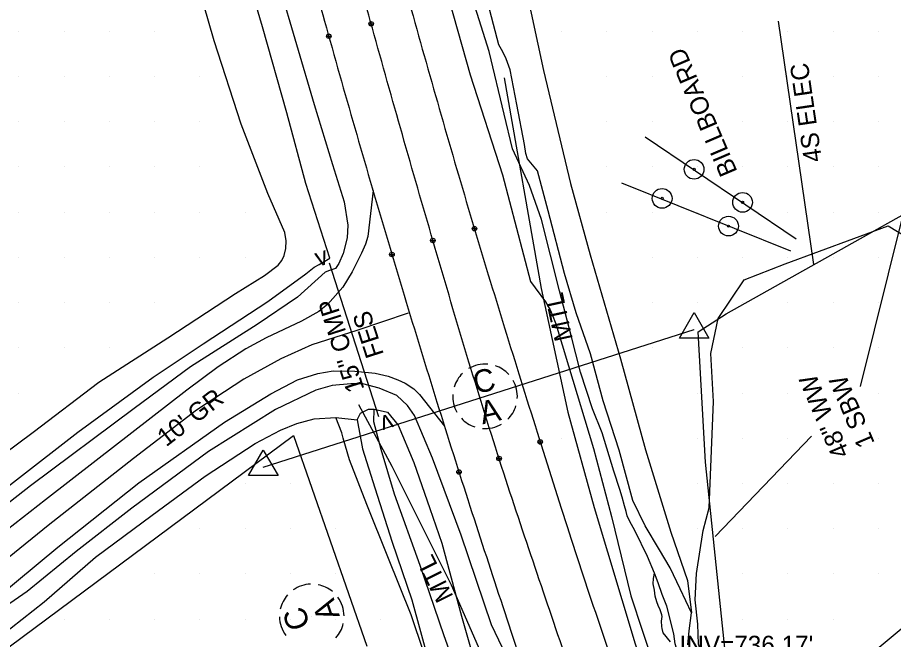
# Model space of a CAD drawing. Extents: x 1548934 to 1561348, y 809680 to 824075.
# Drawn here: x 1551639.7 to 1551833.4, y 810915.5 to 811053 of the extents above; entities that cross this region are included whole.
import ezdxf

# ---------------------------------------------------------------- set-up
doc = ezdxf.new("R2010")
doc.units = 0
for name, color, linetype in [('Default', 7, 'Continuous'), ('E_NCDOT_Vertical_Profile_Ground_Line', 7, 'Continuous'), ('Exist DTM QL2 LIDAR Elevation Point', 7, 'Continuous'), ('Exist Guardrail', 7, 'Continuous'), ('Exist Guardrail Text', 7, 'Continuous'), ('Exist Other Culture Area Outline', 7, 'Continuous'), ('Exist Other Culture Fence Line Leader', 7, 'Continuous'), ('Exist Other Culture Fence Line Text', 7, 'Continuous'), ('Exist Other Culture Sign', 7, 'Continuous'), ('Exist Other Culture Sign CELL', 7, 'Continuous'), ('Exist Other Culture Sign Text', 7, 'Continuous'), ('Exist Right of Way Control of Access CA Symbol CELL', 7, 'Continuous'), ('Exist Roads Soil', 7, 'Continuous'), ('Exist Roads Soil Text', 7, 'Continuous'), ('Exist Structure Minor Culvert Topo', 7, 'Continuous'), ('Exist Structure Minor Culvert Topo Terminator', 7, 'Continuous'), ('Exist Structure Minor Pipes CMP 15 Inch Text', 7, 'Continuous'), ('Exist Structure Minor Pipes CMP 18 Inch Invert Elevation', 7, 'Continuous'), ('Exist Vegetation Woods Line', 7, 'Continuous'), ('P_NCDOT_Vertical_Profile_Grade_Minor_Road', 7, 'Continuous'), ('P_RDY_Dimension_Text', 7, 'Continuous'), ('PH Exist DTM Breakline', 7, 'Continuous')]:
    doc.layers.add(name, color=color, linetype=linetype)

# ---------------------------------------------------------------- blocks, each defined once
blk = doc.blocks.new('SurveyPointCell')
at = {"layer": 'Default'}
for p, q in [((-0.5, 0), (0.5, 0)), ((0, -0.5), (0, 0.5))]:
    blk.add_line(p, q, dxfattribs=at)
blk.add_circle((0, 0), 0.5, dxfattribs=at)

msp = doc.modelspace()

# ---------------------------------------------------------------- linework, layer by layer
at = {"layer": 'E_NCDOT_Vertical_Profile_Ground_Line'}
for p, q in [((1551789.31, 810984.03), (1551789.31, 810984.03)), ((1551694.04, 810953.63), (1551694.04, 810953.63))]:
    msp.add_line(p, q, dxfattribs=at)
for points in [[(1551786.06, 810982.14), (1551789.31, 810987.78), (1551792.56, 810982.14)], [(1551690.79, 810951.74), (1551694.04, 810957.38), (1551697.29, 810951.74)]]:
    msp.add_lwpolyline(points, close=True, dxfattribs=at)
for points in [[(1551669.23, 811277), (1551672.74, 811263.65), (1551679.61, 811234.97), (1551690.37, 811191.22), (1551702.41, 811145.66), (1551714.33, 811100.03), (1551727, 811053.45), (1551740.47, 811006.5), (1551755.13, 810959.34), (1551769.1, 810915.85), (1551778.93, 810888.33), (1551783.17, 810876.09)], [(1551650.09, 811272.18), (1551653.54, 811258.38), (1551661.25, 811229.55), (1551671.78, 811185.41), (1551683.85, 811140.03), (1551696.07, 811094.56), (1551708.62, 811047.91), (1551722.36, 811000.57), (1551736.98, 810952.93), (1551751.55, 810908.96), (1551760.88, 810880.92), (1551765.29, 810868.44)]]:
    msp.add_open_spline(points, degree=3, dxfattribs=at)
at = {"layer": 'Exist DTM QL2 LIDAR Elevation Point'}
for p, q in [((1551639.99, 811050.01), (1551639.99, 811050.01)), ((1551649.99, 811050.01), (1551649.99, 811050.01)), ((1551659.99, 811050.01), (1551659.99, 811050.01)), ((1551669.99, 811050.01), (1551669.99, 811050.01)), ((1551760, 811050.01), (1551760, 811050.01)), ((1551770, 811050.01), (1551770, 811050.01)), ((1551780, 811050.01), (1551780, 811050.01)), ((1551790, 811050.01), (1551790, 811050.01)), ((1551800, 811050.01), (1551800, 811050.01)), ((1551810, 811050.01), (1551810, 811050.01)), ((1551820, 811050.01), (1551820, 811050.01)), ((1551830.01, 811050.01), (1551830.01, 811050.01)), ((1551639.99, 811040.01), (1551639.99, 811040.01)), ((1551649.99, 811040.01), (1551649.99, 811040.01)), ((1551659.99, 811040.01), (1551659.99, 811040.01)), ((1551669.99, 811040.01), (1551669.99, 811040.01)), ((1551679.99, 811040.01), (1551679.99, 811040.01)), ((1551770, 811040.01), (1551770, 811040.01)), ((1551780, 811040.01), (1551780, 811040.01)), ((1551790, 811040.01), (1551790, 811040.01)), ((1551800, 811040.01), (1551800, 811040.01)), ((1551810, 811040.01), (1551810, 811040.01)), ((1551820, 811040.01), (1551820, 811040.01)), ((1551830.01, 811040.01), (1551830.01, 811040.01)), ((1551639.99, 811030.01), (1551639.99, 811030.01)), ((1551649.99, 811030.01), (1551649.99, 811030.01)), ((1551659.99, 811030.01), (1551659.99, 811030.01)), ((1551669.99, 811030.01), (1551669.99, 811030.01)), ((1551679.99, 811030.01), (1551679.99, 811030.01)), ((1551770, 811030.01), (1551770, 811030.01)), ((1551780, 811030.01), (1551780, 811030.01)), ((1551790, 811030.01), (1551790, 811030.01)), ((1551800, 811030.01), (1551800, 811030.01)), ((1551810, 811030.01), (1551810, 811030.01)), ((1551820, 811030.01), (1551820, 811030.01)), ((1551830.01, 811030.01), (1551830.01, 811030.01)), ((1551639.99, 811020.01), (1551639.99, 811020.01)), ((1551649.99, 811020.01), (1551649.99, 811020.01)), ((1551659.99, 811020.01), (1551659.99, 811020.01)), ((1551669.99, 811020.01), (1551669.99, 811020.01)), ((1551679.99, 811020.01), (1551679.99, 811020.01)), ((1551770, 811020.01), (1551770, 811020.01)), ((1551780, 811020.01), (1551780, 811020.01)), ((1551790, 811020.01), (1551790, 811020.01)), ((1551800, 811020.01), (1551800, 811020.01)), ((1551810, 811020.01), (1551810, 811020.01)), ((1551820, 811020.01), (1551820, 811020.01)), ((1551830.01, 811020.01), (1551830.01, 811020.01)), ((1551639.99, 811010.01), (1551639.99, 811010.01)), ((1551649.99, 811010.01), (1551649.99, 811010.01)), ((1551659.99, 811010.01), (1551659.99, 811010.01)), ((1551669.99, 811010.01), (1551669.99, 811010.01)), ((1551679.99, 811010.01), (1551679.99, 811010.01)), ((1551689.99, 811010.01), (1551689.99, 811010.01)), ((1551770, 811010.01), (1551770, 811010.01)), ((1551780, 811010.01), (1551780, 811010.01)), ((1551790, 811010.01), (1551790, 811010.01)), ((1551800, 811010.01), (1551800, 811010.01)), ((1551810, 811010.01), (1551810, 811010.01)), ((1551820, 811010.01), (1551820, 811010.01)), ((1551830.01, 811010.01), (1551830.01, 811010.01)), ((1551639.99, 811000.01), (1551639.99, 811000.01)), ((1551649.99, 811000.01), (1551649.99, 811000.01)), ((1551659.99, 811000.01), (1551659.99, 811000.01)), ((1551669.99, 811000.01), (1551669.99, 811000.01)), ((1551679.99, 811000.01), (1551679.99, 811000.01)), ((1551689.99, 811000.01), (1551689.99, 811000.01)), ((1551780, 811000.01), (1551780, 811000.01)), ((1551790, 811000.01), (1551790, 811000.01)), ((1551800, 811000.01), (1551800, 811000.01)), ((1551810, 811000.01), (1551810, 811000.01)), ((1551820, 811000.01), (1551820, 811000.01)), ((1551830.01, 811000.01), (1551830.01, 811000.01)), ((1551639.99, 810990.01), (1551639.99, 810990.01)), ((1551649.99, 810990.01), (1551649.99, 810990.01)), ((1551659.99, 810990.01), (1551659.99, 810990.01)), ((1551669.99, 810990.01), (1551669.99, 810990.01)), ((1551780, 810990.01), (1551780, 810990.01)), ((1551790, 810990.01), (1551790, 810990.01)), ((1551800, 810990.01), (1551800, 810990.01)), ((1551810, 810990.01), (1551810, 810990.01)), ((1551820, 810990.01), (1551820, 810990.01)), ((1551830.01, 810990.01), (1551830.01, 810990.01)), ((1551639.99, 810980.01), (1551639.99, 810980.01)), ((1551649.99, 810980.01), (1551649.99, 810980.01)), ((1551659.99, 810980.01), (1551659.99, 810980.01)), ((1551780, 810980.01), (1551780, 810980.01)), ((1551790, 810980.01), (1551790, 810980.01)), ((1551800, 810980.01), (1551800, 810980.01)), ((1551810, 810980.01), (1551810, 810980.01)), ((1551820, 810980.01), (1551820, 810980.01)), ((1551830.01, 810980.01), (1551830.01, 810980.01)), ((1551639.99, 810970.01), (1551639.99, 810970.01)), ((1551790, 810970.01), (1551790, 810970.01)), ((1551800, 810970.01), (1551800, 810970.01)), ((1551810, 810970.01), (1551810, 810970.01)), ((1551820, 810970.01), (1551820, 810970.01)), ((1551830.01, 810970.01), (1551830.01, 810970.01)), ((1551760, 810960.01), (1551760, 810960.01)), ((1551790, 810960.01), (1551790, 810960.01)), ((1551800, 810960.01), (1551800, 810960.01)), ((1551810, 810960.01), (1551810, 810960.01)), ((1551820, 810960.01), (1551820, 810960.01)), ((1551830.01, 810960.01), (1551830.01, 810960.01)), ((1551689.99, 810950.01), (1551689.99, 810950.01)), ((1551699.99, 810950.01), (1551699.99, 810950.01)), ((1551790, 810950.01), (1551790, 810950.01)), ((1551800, 810950.01), (1551800, 810950.01)), ((1551810, 810950.01), (1551810, 810950.01)), ((1551820, 810950.01), (1551820, 810950.01)), ((1551830.01, 810950.01), (1551830.01, 810950.01)), ((1551679.99, 810940.01), (1551679.99, 810940.01)), ((1551689.99, 810940.01), (1551689.99, 810940.01)), ((1551699.99, 810940.01), (1551699.99, 810940.01)), ((1551710, 810940.01), (1551710, 810940.01)), ((1551790, 810940.01), (1551790, 810940.01)), ((1551800, 810940.01), (1551800, 810940.01)), ((1551810, 810940.01), (1551810, 810940.01)), ((1551820, 810940.01), (1551820, 810940.01)), ((1551830.01, 810940.01), (1551830.01, 810940.01)), ((1551669.99, 810930.01), (1551669.99, 810930.01)), ((1551679.99, 810930.01), (1551679.99, 810930.01)), ((1551689.99, 810930.01), (1551689.99, 810930.01)), ((1551699.99, 810930.01), (1551699.99, 810930.01)), ((1551710, 810930.01), (1551710, 810930.01)), ((1551800, 810930.01), (1551800, 810930.01)), ((1551810, 810930.01), (1551810, 810930.01)), ((1551820, 810930.01), (1551820, 810930.01)), ((1551830.01, 810930.01), (1551830.01, 810930.01)), ((1551649.99, 810920), (1551649.99, 810920)), ((1551659.99, 810920), (1551659.99, 810920)), ((1551669.99, 810920), (1551669.99, 810920)), ((1551679.99, 810920), (1551679.99, 810920)), ((1551689.99, 810920), (1551689.99, 810920)), ((1551699.99, 810920), (1551699.99, 810920)), ((1551710, 810920), (1551710, 810920)), ((1551720, 810920), (1551720, 810920)), ((1551800, 810920), (1551800, 810920)), ((1551810, 810920), (1551810, 810920)), ((1551820, 810920), (1551820, 810920))]:
    msp.add_line(p, q, dxfattribs=at)
at = {"layer": 'Exist Guardrail'}
for points in [[(1551747.29, 811039.69), (1551755.45, 810993.12), (1551761.38, 810965.78), (1551767.15, 810944.71), (1551776.25, 810914.57), (1551788.66, 810877.39)], [(1551764.14, 810855.59), (1551754.13, 810881.81), (1551744.16, 810908), (1551735.65, 810927.52), (1551722.54, 810953.77), (1551715.12, 810967.41)]]:
    msp.add_lwpolyline(points, dxfattribs=at)
at = {"layer": 'Exist Other Culture Area Outline'}
for p, q in [((1551631, 810908.82), (1551700.72, 810960.62)), ((1551700.72, 810960.62), (1551716.92, 810914))]:
    msp.add_line(p, q, dxfattribs=at)
at = {"layer": 'Exist Other Culture Fence Line Leader'}
for p, q in [((1551835.26, 811008.8), (1551825.95, 810971.44)), ((1551793.9, 810938.25), (1551815.26, 810960.49))]:
    msp.add_line(p, q, dxfattribs=at)
at = {"layer": 'Exist Other Culture Sign'}
for p, q in [((1551778.45, 811026.64), (1551811.85, 811004.1)), ((1551810.64, 811001.37), (1551773.3, 811016.41))]:
    msp.add_line(p, q, dxfattribs=at)
at = {"layer": 'Exist Other Culture Sign CELL'}
for centre, radius in [((1551789.28, 811019.47), 2.18), ((1551789.28, 811019.47), 0.24), ((1551782.21, 811013.04), 2.18), ((1551799.99, 811012.17), 2.18), ((1551782.21, 811013.04), 0.24), ((1551799.99, 811012.17), 0.24), ((1551796.88, 811006.91), 2.18), ((1551796.88, 811006.91), 0.24)]:
    msp.add_circle(centre, radius, dxfattribs=at)
at = {"layer": 'Exist Right of Way Control of Access CA Symbol CELL'}
for p, q in [((1551694.04, 810953.63), (1551789.31, 810984.03)), ((1551743.06, 810969.27), (1551743.06, 810969.27)), ((1551704.75, 810920.62), (1551704.75, 810920.62))]:
    msp.add_line(p, q, dxfattribs=at)
for centre, start, end in [((1551743.06, 810969.27), 85.2107, 120.8229), ((1551743.06, 810969.27), 42.8294, 71.4172), ((1551743.06, 810969.27), 134.6163, 163.2042), ((1551743.06, 810969.27), 356.4374, 29.5962), ((1551743.06, 810969.27), 176.4374, 209.5962), ((1551743.06, 810969.27), 314.6163, 343.2042), ((1551743.06, 810969.27), 222.8294, 251.4172), ((1551743.06, 810969.27), 265.2107, 300.8229), ((1551704.75, 810920.62), 92.0378, 125.1966), ((1551704.75, 810920.62), 50.2168, 78.8046), ((1551704.75, 810920.62), 138.4298, 167.0177), ((1551704.75, 810920.62), 0.8111, 36.4233), ((1551704.75, 810920.62), 180.8111, 216.4233), ((1551704.75, 810920.62), 318.4298, 347.0177)]:
    msp.add_arc(centre, 7.14, start, end, dxfattribs=at)
at = {"layer": 'Exist Roads Soil'}
for points in [[(1551718.29, 811014.76), (1551717.13, 811004.65), (1551716.65, 811002.91), (1551715.75, 811000.9), (1551713.71, 810996.82), (1551711.61, 810993.39), (1551708.31, 810989.66), (1551706.28, 810988), (1551702.5, 810985.86), (1551694.7, 810982.23), (1551690.18, 810979.78), (1551684.09, 810975.77), (1551677.11, 810970.61), (1551657.11, 810955.12), (1551645.88, 810946.36), (1551633.92, 810937.07)], [(1551629.82, 810920.36), (1551648.6, 810935.94), (1551666.49, 810950.15), (1551685.46, 810963.53), (1551695.73, 810969.82), (1551701.62, 810972.91), (1551706.1, 810974.33), (1551709.46, 810974.92), (1551714.28, 810974.87), (1551718.79, 810974.38), (1551721.67, 810973.73), (1551723.76, 810972.92), (1551725.42, 810972.19), (1551727.32, 810970.92), (1551728.53, 810969.7), (1551734.07, 810962.71)]]:
    msp.add_lwpolyline(points, dxfattribs=at)
at = {"layer": 'Exist Structure Minor Culvert Topo'}
msp.add_line((1551719.55, 810964.73), (1551708.68, 810998.7), dxfattribs=at)
at = {"layer": 'Exist Vegetation Woods Line'}
for points in [[(1551842.25, 810881.19), (1551829.67, 810873.37), (1551822.69, 810873.27), (1551815.92, 810885.9), (1551815.5, 810886.67), (1551807.41, 810888.02), (1551806.22, 810887.92), (1551800.5, 810889.93), (1551797.54, 810895.02), (1551794.74, 810901.84), (1551792.64, 810907.53), (1551790.26, 810914.5), (1551790.13, 810918.88), (1551789.49, 810924.31), (1551789.81, 810930.06), (1551791.28, 810939.57), (1551792.61, 810944.6), (1551793.56, 810968.12), (1551792.97, 810978.75), (1551794.6, 810986.48), (1551800.37, 810995.02), (1551809.38, 810998.56), (1551832.14, 811006.96)], [(1551832.14, 811006.96), (1551840.03, 811002.19)]]:
    msp.add_lwpolyline(points, dxfattribs=at)
at = {"layer": 'P_NCDOT_Vertical_Profile_Grade_Minor_Road'}
msp.add_open_spline([(1551774.27, 810871.88), (1551769.96, 810884.28), (1551760.75, 810912.23), (1551745.66, 810955.91), (1551731.5, 811003.54), (1551718, 811050.78), (1551705.43, 811097.26), (1551693.24, 811142.66), (1551681.43, 811187.98), (1551670.2, 811231.95), (1551663.06, 811260.98), (1551659.56, 811274.89)], degree=3, dxfattribs=at)
at = {"layer": 'P_RDY_Dimension_Text'}
msp.add_line((1551815.74, 810998.4), (1551807.93, 811052.21), dxfattribs=at)
msp.add_lwpolyline([(1551792.63, 810879.89), (1551798.87, 810886.61), (1551791.81, 810954.68), (1551790.16, 810983.57), (1551796.35, 810987.52), (1551966.16, 811082.82)], dxfattribs=at)
at = {"layer": 'PH Exist DTM Breakline'}
for points in [[(1551625.86, 810940.3), (1551653.05, 810961.36), (1551669.7, 810973.54), (1551680.77, 810980.85), (1551695.07, 810990.25), (1551703.46, 810996.36), (1551705.28, 810997.82), (1551706.41, 810998.42), (1551708.74, 810999.85), (1551703.45, 811016.33), (1551699.21, 811031.98), (1551693.84, 811050.96), (1551687.88, 811071.22), (1551681.52, 811095.77), (1551674.77, 811122.66), (1551667.66, 811150.4), (1551661.81, 811173.23), (1551655.99, 811197.83), (1551650.7, 811220.08), (1551647.84, 811234.57), (1551643.86, 811252.56), (1551641.25, 811265.31), (1551638.41, 811278.13)], [(1551740.58, 811092.26), (1551743.29, 811086.68), (1551747.2, 811076.34), (1551751.97, 811059.91), (1551756, 811041.33), (1551761.97, 811016.35), (1551766.27, 811000.56), (1551772.99, 810977.55), (1551778.52, 810957.45), (1551784.14, 810939.23), (1551787.8, 810928.56), (1551788.72, 810921.41)], [(1551623.45, 810946.73), (1551643.13, 810961.35), (1551657.71, 810972.39), (1551672.91, 810982.24), (1551687.86, 810992), (1551694.31, 810995.97), (1551697.32, 810998.26), (1551698.16, 810999.32), (1551698.63, 811000.4), (1551699.02, 811001.94), (1551699.07, 811003.65), (1551698.78, 811005.52), (1551695.07, 811014.09), (1551689.11, 811029.43), (1551683.15, 811047.86), (1551678.6, 811063.82)], [(1551787.92, 810914.29), (1551788.2, 810917.45), (1551788.72, 810921.41), (1551786.22, 810926.7), (1551783.99, 810931.36), (1551781.62, 810935.34), (1551778.44, 810940.63), (1551775.75, 810946.23), (1551772.71, 810957.36), (1551769.2, 810968.28), (1551766.36, 810978.7), (1551763.22, 810987.74), (1551760.64, 810996.47), (1551756.99, 811010.31), (1551754.62, 811019.12), (1551752.43, 811021.78), (1551752.1, 811022.99), (1551751.75, 811024.97), (1551750.09, 811033.79), (1551748.6, 811041.48), (1551747.76, 811043.93), (1551746.97, 811045.44), (1551746.11, 811047.01), (1551742.09, 811062.23)], [(1551697.49, 811060.44), (1551705.26, 811033.84), (1551709.33, 811020.53), (1551711.94, 811012.28), (1551712.72, 811007.13), (1551712.61, 811004.35), (1551711.7, 811000.87), (1551710.77, 810998.65), (1551709.96, 810997.53), (1551708.7, 810997.1), (1551707.69, 810996.75), (1551701.57, 810991.21), (1551692.67, 810985.14), (1551677.93, 810975.8), (1551665.46, 810966.6), (1551642.56, 810949.47), (1551619.76, 810931.61)], [(1551734.17, 811060.29), (1551739.78, 811040.33), (1551746.93, 811018.26), (1551753.09, 810994.66), (1551756.45, 810990.16), (1551757.42, 810988.4), (1551757.91, 810987.38), (1551758.68, 810985.27), (1551761.52, 810976.04), (1551767.02, 810957.73), (1551771.03, 810942.69), (1551775.29, 810925.19), (1551780.42, 810909.54), (1551786.36, 810889.7)], [(1551784.02, 810915.01), (1551782.47, 810916.99), (1551782.23, 810917.95), (1551782.17, 810918.39), (1551782.06, 810919.53), (1551782.2, 810920.58), (1551782.11, 810920.96), (1551781.78, 810922.08), (1551781.36, 810923.03), (1551781.04, 810923.83), (1551780.66, 810925.07), (1551780.49, 810926.38), (1551780.23, 810927.79), (1551780.27, 810928.99), (1551780.51, 810930.17), (1551778.94, 810933.82), (1551776.23, 810939.46), (1551775, 810941.73), (1551774.51, 810942.88), (1551774.23, 810943.84), (1551773.86, 810945.07), (1551773.39, 810946.96), (1551772.84, 810948.69), (1551771.56, 810952.72), (1551768.92, 810961.21), (1551766.78, 810966.53), (1551764.19, 810974.63), (1551762.13, 810982.76), (1551759.54, 810992.59), (1551755.52, 811008.34), (1551752.88, 811015.92), (1551749.16, 811023.99), (1551747.25, 811031.68), (1551743.97, 811045.5), (1551740.88, 811055.34)], [(1551964.87, 811011.81), (1551950.05, 811001.19), (1551928.64, 810985.19), (1551911.37, 810973.98), (1551899.79, 810966.08), (1551880.25, 810951.2), (1551869.51, 810942.95), (1551844.01, 810925.31), (1551827.48, 810911.47), (1551810.29, 810896.27), (1551800.43, 810887.11), (1551798.7, 810886.52), (1551796.47, 810886.72), (1551794.87, 810885.71)], [(1551726.07, 810987.63), (1551714.72, 810983.85), (1551704.75, 810980.66), (1551697.9, 810977.6), (1551689.75, 810973.07), (1551679.24, 810966.2), (1551665.31, 810955.49), (1551646.45, 810940.69), (1551627.97, 810925.75), (1551614.84, 810916.02), (1551606.45, 810911.08), (1551604.44, 810910.12), (1551601.05, 810909.28), (1551591.96, 810907.48), (1551583.41, 810907.17), (1551576.77, 810907.65), (1551568.84, 810909.78), (1551562.19, 810913.41), (1551552.65, 810920.44), (1551544.29, 810928.79), (1551536.7, 810936.36)], [(1551756.6, 810893.45), (1551744.48, 810918.77), (1551737.77, 810938.57), (1551731.45, 810955.6), (1551727.45, 810965), (1551725.9, 810967.28), (1551723.52, 810969.49), (1551719.68, 810971.06), (1551716.03, 810972.06), (1551713.36, 810972.06), (1551709.28, 810971.65), (1551705.62, 810970.61), (1551696.74, 810966.37), (1551681.91, 810957.07), (1551664.96, 810944.51), (1551652.69, 810934.96), (1551641.8, 810926.1), (1551621.87, 810912.31)], [(1551635.81, 810916.17), (1551645.58, 810923.81), (1551656.97, 810933.69), (1551669.46, 810943.03), (1551681.22, 810951.63), (1551692.25, 810958.85), (1551697.87, 810961.76), (1551701.43, 810963.27), (1551705.3, 810964.31), (1551710.05, 810964.6), (1551714.79, 810964.11), (1551715.49, 810965.55), (1551717.3, 810966.45), (1551718.53, 810966.43), (1551721.51, 810965.76), (1551723.82, 810962.9), (1551727.34, 810954.67), (1551730.84, 810944.47), (1551733.47, 810936.79), (1551737.87, 810920.64), (1551741.23, 810908.78)], [(1551744.21, 810886.86), (1551739.95, 810899.84), (1551734.01, 810916.31), (1551728.73, 810931.9), (1551723.05, 810947.61), (1551720.07, 810957.53), (1551718.47, 810963.63), (1551718.53, 810966.43)], [(1551732.43, 810904.08), (1551726.71, 810920.97), (1551721.56, 810933.77), (1551716.96, 810945.35), (1551713.09, 810955.21), (1551711.66, 810960), (1551711.4, 810961.17), (1551710.05, 810964.6)], [(1551714.79, 810964.11), (1551716, 810957.7), (1551718.68, 810949.05), (1551722.53, 810937), (1551726.88, 810924.28), (1551732.43, 810904.08)], [(1551786.01, 810911.39), (1551785.09, 810914.56), (1551784.76, 810916.72), (1551783.21, 810922.85), (1551782.22, 810925.47), (1551781.3, 810928.03), (1551780.51, 810930.17)]]:
    msp.add_lwpolyline(points, dxfattribs=at)

# ---------------------------------------------------------------- block references
at = {"layer": 'Default'}
for p in [(1551717.87, 811051.66), (1551708.51, 811048.9), (1551740.71, 811006.35), (1551731.53, 811003.74), (1551722.47, 811000.64), (1551755.26, 810959.19), (1551746.16, 810955.54), (1551737.3, 810952.53)]:
    msp.add_blockref('SurveyPointCell', p, dxfattribs=at)

# ---------------------------------------------------------------- texts
at = {"layer": 'Exist Guardrail Text'}
for rotation, p in [(102.2307, (1551762.47, 810981.96)), (116.4593, (1551736.14, 810925))]:
    msp.add_text('MTL', height=4.02, rotation=rotation, dxfattribs=at).set_placement(p)
at = {"layer": 'Exist Other Culture Fence Line Text'}
for s, rotation, p in [('4S ELEC', 98.2653, (1551817.59, 811021.34)), ('48" WW', 113.1736, (1551823.73, 810956.59)), ('1 SBW', 113.1736, (1551829.28, 810958.96))]:
    msp.add_text(s, height=4.02, rotation=rotation, dxfattribs=at).set_placement(p)
at = {"layer": 'Exist Other Culture Sign Text'}
msp.add_text('BILLBOARD', height=4.02, rotation=113.1736, dxfattribs=at).set_placement((1551798.91, 811018.98))
at = {"layer": 'Exist Right of Way Control of Access CA Symbol CELL'}
for s, rotation, p in [('C', 13.0168, (1551741.03, 810969.76)), ('A', 13.0168, (1551742.5, 810963.06)), ('A', 108.6172, (1551710.98, 810920.67)), ('C', 108.6172, (1551704.47, 810918.55))]:
    msp.add_text(s, height=5, rotation=rotation, dxfattribs=at).set_placement(p)
at = {"layer": 'Exist Roads Soil Text'}
msp.add_text("10' GR", height=4.02, rotation=37.7719, dxfattribs=at).set_placement((1551672.56, 810957.98))
at = {"layer": 'Exist Structure Minor Culvert Topo Terminator'}
for rotation, p in [(17.7446, (1551706.16, 810997.89)), (197.7446, (1551722.07, 810965.53))]:
    msp.add_text('v', height=4, rotation=rotation, dxfattribs=at).set_placement(p)
at = {"layer": 'Exist Structure Minor Pipes CMP 15 Inch Text'}
for s, p in [('15" CMP', (1551716.42, 810970.89)), ('    FES', (1551722.54, 810972.85))]:
    msp.add_text(s, height=4.02, rotation=107.7446, dxfattribs=at).set_placement(p)
at = {"layer": 'Exist Structure Minor Pipes CMP 18 Inch Invert Elevation'}
msp.add_text("INV=736.17'", height=4.02, rotation=360, dxfattribs=at).set_placement((1551786.05, 810912.31))

doc.saveas('drawing.dxf')
